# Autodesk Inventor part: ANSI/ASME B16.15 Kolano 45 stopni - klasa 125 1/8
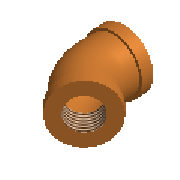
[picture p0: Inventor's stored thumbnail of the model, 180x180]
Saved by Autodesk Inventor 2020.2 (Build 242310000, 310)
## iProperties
Manager: www.cadconsulting.pl
Company: Fabian Stasiak CAD Consulting
NAME: PIPING: ANSI/ASME B16.15 45 Deg Elbow - Class 125
DATA: <meta><inlinegroups number="0" deflen="0"></inlinegroups><connections number="2"></connections><angles><a>2.35619449019234</a></angles></meta>
IsCustomPart: 0
Created: 2014-02
Part Number: ANSI/ASME B16.15 Kolano 45 stopni - klasa 125 1/8
Material: Brąz, odlew
Description: Kolano 45º odlewane z brązu, gwintowane - klasa 125
Document SubType Name: Modeling
Standard: ANSI/ASME B16.15
Designer: F.Stasiak
Standard Revision: 1985
Standards Organization: ANSI
Language: pl-PL
Size Designation: 1/8
Categories: <MemberInstance><Categories><Category DisplayName="Rury cienko- i grubościenne" InternalName="4347fa0f-2144-441d-94cd-e3e15c92b736" Mnemonic="TUBEANDPIPE"><Cate
Density: 1 g/cm^3
Appearance: Brąz - satynowy
Catalog Web Link: www.expertbooks.pl
Author: F.Stasiak
Subject: Zbiór ćwiczeń. Autodesk Inventor 2020. Kurs Professional
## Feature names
1. Revolution1
2. Sweep1
3. Revolution2
## Parameters: MD = 8.73684 mm, C1 = 10.668 mm, B = 6.35 mm, G = 2.032 mm, F1 = 11.176 mm, d6 = 8.73684 mm, d7 = 15.24 mm, d8 = 17.018 mm, d9 = 3.556 mm, d10 = 6.35 mm, d11 = 0.3124 mm, d16 = 90 deg, d17 = 11.176 mm, d18 = 15.24 mm, d30 = 135 deg, d31 = 10.668 mm, d32 = 4.318 mm, d33 = 0, d45 = 0.3124 mm, d46 = 6.35 mm, d47 = 3.556 mm, d48 = 8.73684 mm, d49 = 15.24 mm, d50 = 17.018 mm, d51 = 90 deg, d58 = 6.35 mm, d59 = 0, d60 = 25.4 mm, d61 = 0, H = 17.018 mm, E1 = 3.556 mm, d63 = 0, Size_Designation = 1.25 mm
